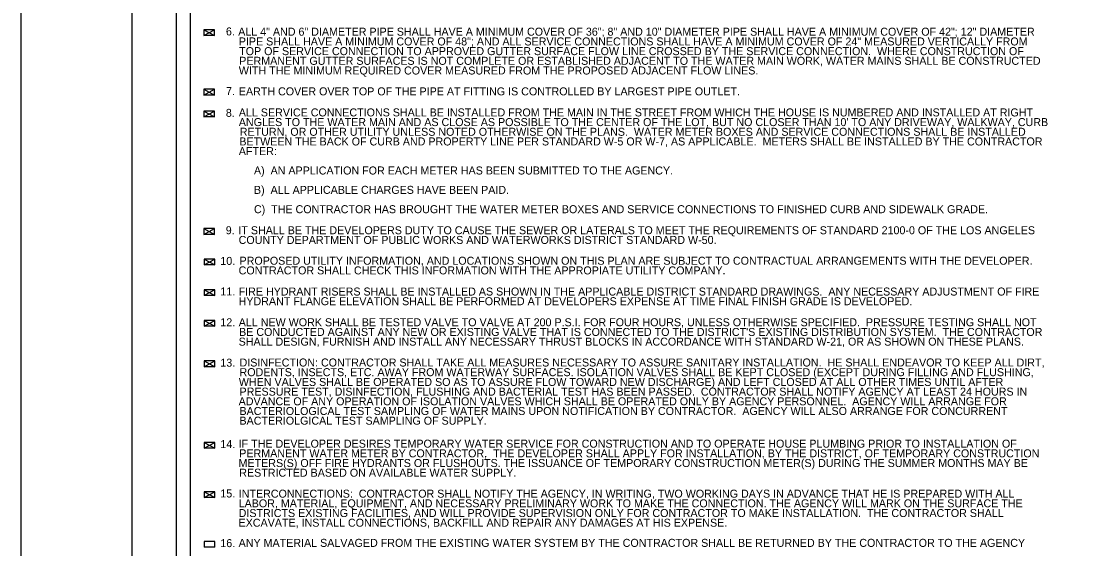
# Model space of a CAD drawing. Extents: x 837 to 1117, y 1316 to 1424.
# Drawn here: x 841.77 to 853.59, y 1410.3 to 1416.23 of the extents above; entities that cross this region are included whole.
import ezdxf

# ---------------------------------------------------------------- set-up
doc = ezdxf.new("R2010")
doc.units = 0
for name, color, linetype in [('0 (Construction)', 7, 'Continuous'), ('BASEMAP', 7, 'Continuous'), ('LLINES', 7, 'Continuous'), ('TEXT', 7, 'Continuous')]:
    doc.layers.add(name, color=color, linetype=linetype)

msp = doc.modelspace()

# ---------------------------------------------------------------- linework, layer by layer
at = {"layer": '0 (Construction)'}
msp.add_lwpolyline([(841.77, 1422.24), (877.77, 1422.24), (877.77, 1398.24), (841.77, 1398.24)], close=True, dxfattribs=at)
at = {"layer": 'BASEMAP'}
for p, q in [((843.02, 1399.24), (843.02, 1421.24)), ((843.52, 1399.74), (843.52, 1420.74)), ((843.678, 1399.867), (843.678, 1420.065))]:
    msp.add_line(p, q, dxfattribs=at)
at = {"layer": 'LLINES'}
for p, q in [((843.828, 1416.133), (843.948, 1416.069)), ((843.828, 1416.133), (843.828, 1416.069)), ((843.828, 1416.069), (843.948, 1416.133)), ((843.948, 1416.133), (843.828, 1416.133)), ((843.948, 1416.069), (843.828, 1416.069)), ((843.948, 1416.069), (843.948, 1416.133)), ((843.828, 1415.397), (843.948, 1415.462)), ((843.828, 1415.462), (843.828, 1415.397)), ((843.828, 1415.462), (843.948, 1415.397)), ((843.948, 1415.462), (843.828, 1415.462)), ((843.948, 1415.397), (843.828, 1415.397)), ((843.948, 1415.397), (843.948, 1415.462)), ((843.828, 1415.152), (843.948, 1415.216)), ((843.828, 1415.216), (843.948, 1415.152)), ((843.948, 1415.216), (843.828, 1415.216)), ((843.828, 1415.216), (843.828, 1415.152)), ((843.948, 1415.152), (843.828, 1415.152)), ((843.948, 1415.152), (843.948, 1415.216)), ((843.827, 1413.829), (843.946, 1413.894)), ((843.827, 1413.894), (843.827, 1413.829)), ((843.827, 1413.894), (843.946, 1413.829)), ((843.946, 1413.894), (843.827, 1413.894)), ((843.946, 1413.829), (843.827, 1413.829)), ((843.946, 1413.829), (843.946, 1413.894)), ((843.949, 1413.55), (843.83, 1413.55)), ((843.83, 1413.55), (843.949, 1413.485)), ((843.83, 1413.55), (843.83, 1413.485)), ((843.83, 1413.485), (843.949, 1413.55)), ((843.949, 1413.485), (843.83, 1413.485)), ((843.949, 1413.485), (843.949, 1413.55)), ((843.83, 1413.206), (843.83, 1413.141)), ((843.949, 1413.206), (843.83, 1413.206)), ((843.949, 1413.141), (843.83, 1413.141)), ((843.949, 1413.141), (843.949, 1413.206)), ((843.949, 1412.858), (843.83, 1412.858)), ((843.83, 1412.858), (843.949, 1412.794)), ((843.83, 1412.858), (843.83, 1412.794)), ((843.83, 1412.794), (843.949, 1412.858)), ((843.949, 1412.794), (843.83, 1412.794)), ((843.949, 1412.794), (843.949, 1412.858)), ((843.83, 1412.339), (843.949, 1412.404)), ((843.83, 1412.404), (843.83, 1412.339)), ((843.83, 1412.404), (843.949, 1412.339)), ((843.949, 1412.404), (843.83, 1412.404)), ((843.949, 1412.339), (843.949, 1412.404)), ((843.949, 1412.339), (843.83, 1412.339)), ((843.949, 1411.487), (843.83, 1411.487)), ((843.83, 1411.487), (843.949, 1411.422)), ((843.83, 1411.487), (843.83, 1411.422)), ((843.83, 1411.422), (843.949, 1411.487)), ((843.949, 1411.422), (843.949, 1411.487)), ((843.949, 1411.422), (843.83, 1411.422)), ((843.83, 1410.866), (843.949, 1410.93)), ((843.83, 1410.93), (843.83, 1410.866)), ((843.83, 1410.93), (843.949, 1410.866)), ((843.949, 1410.93), (843.83, 1410.93)), ((843.949, 1410.866), (843.83, 1410.866)), ((843.949, 1410.866), (843.949, 1410.93)), ((843.949, 1410.372), (843.83, 1410.372)), ((843.83, 1410.372), (843.83, 1410.307)), ((843.949, 1410.307), (843.83, 1410.307)), ((843.949, 1410.307), (843.949, 1410.372))]:
    msp.add_line(p, q, dxfattribs=at)
at = {"layer": 'TEXT'}
for p, q in [((843.949, 1413.206), (843.83, 1413.141)), ((843.83, 1413.206), (843.949, 1413.141))]:
    msp.add_line(p, q, dxfattribs=at)

# ---------------------------------------------------------------- texts
at = {"layer": 'LLINES'}
for s, p in [('6.', (844.075, 1416.069)), ('ALL 4" AND 6" DIAMETER PIPE SHALL HAVE A MINIMUM COVER OF 36"; 8" AND 10" DIAMETER PIPE SHALL HAVE A MINIMUM COVER OF 42"; 12" DIAMETER', (844.213, 1416.066)), ('TOP OF SERVICE CONNECTION TO APPROVED GUTTER SURFACE FLOW LINE CROSSED BY THE SERVICE CONNECTION.  WHERE CONSTRUCTION OF', (844.224, 1415.847)), ('PIPE SHALL HAVE A MINIMUM COVER OF 48"; AND ALL SERVICE CONNECTIONS SHALL HAVE A MINIMUM COVER OF 24" MEASURED VERTICALLY FROM', (844.22, 1415.956)), ('PERMANENT GUTTER SURFACES IS NOT COMPLETE OR ESTABLISHED ADJACENT TO THE WATER MAIN WORK, WATER MAINS SHALL BE CONSTRUCTED', (844.225, 1415.738)), ('WITH THE MINIMUM REQUIRED COVER MEASURED FROM THE PROPOSED ADJACENT FLOW LINES.', (844.22, 1415.629)), ('7.', (844.076, 1415.397)), ('EARTH COVER OVER TOP OF THE PIPE AT FITTING IS CONTROLLED BY LARGEST PIPE OUTLET.', (844.22, 1415.394)), ('8.', (844.074, 1415.152)), ('ALL SERVICE CONNECTIONS SHALL BE INSTALLED FROM THE MAIN IN THE STREET FROM WHICH THE HOUSE IS NUMBERED AND INSTALLED AT RIGHT', (844.22, 1415.157)), ("ANGLES TO THE WATER MAIN AND AS CLOSE AS POSSIBLE TO THE CENTER OF THE LOT, BUT NO CLOSER THAN 10' TO ANY DRIVEWAY, WALKWAY, CURB", (844.22, 1415.048)), ('RETURN, OR OTHER UTILITY UNLESS NOTED OTHERWISE ON THE PLANS.  WATER METER BOXES AND SERVICE CONNECTIONS SHALL BE INSTALLED', (844.231, 1414.939)), ('BETWEEN THE BACK OF CURB AND PROPERTY LINE PER STANDARD W-5 OR W-7, AS APPLICABLE.  METERS SHALL BE INSTALLED BY THE CONTRACTOR', (844.226, 1414.83)), ('AFTER:', (844.22, 1414.721)), ('     A)  AN APPLICATION FOR EACH METER HAS BEEN SUBMITTED TO THE AGENCY.', (844.223, 1414.503)), ('     B)  ALL APPLICABLE CHARGES HAVE BEEN PAID.', (844.223, 1414.285)), ('     C)  THE CONTRACTOR HAS BROUGHT THE WATER METER BOXES AND SERVICE CONNECTIONS TO FINISHED CURB AND SIDEWALK GRADE.', (844.223, 1414.067)), ('9.', (844.073, 1413.83)), ('COUNTY DEPARTMENT OF PUBLIC WORKS AND WATERWORKS DISTRICT STANDARD W-50.', (844.218, 1413.721)), ('IT SHALL BE THE DEVELOPERS DUTY TO CAUSE THE SEWER OR LATERALS TO MEET THE REQUIREMENTS OF STANDARD 2100-0 OF THE LOS ANGELES', (844.215, 1413.83)), ('10.', (844.012, 1413.485)), ('PROPOSED UTILITY INFORMATION, AND LOCATIONS SHOWN ON THIS PLAN ARE SUBJECT TO CONTRACTUAL ARRANGEMENTS WITH THE DEVELOPER.', (844.228, 1413.487)), ('CONTRACTOR SHALL CHECK THIS INFORMATION WITH THE APPROPIATE UTILITY COMPANY.', (844.218, 1413.378)), ('11.', (844.012, 1413.141)), ('FIRE HYDRANT RISERS SHALL BE INSTALLED AS SHOWN IN THE APPLICABLE DISTRICT STANDARD DRAWINGS.  ANY NECESSARY ADJUSTMENT OF FIRE', (844.218, 1413.14)), ('HYDRANT FLANGE ELEVATION SHALL BE PERFORMED AT DEVELOPERS EXPENSE AT TIME FINAL FINISH GRADE IS DEVELOPED.', (844.218, 1413.031)), ('12.', (844.012, 1412.794)), ('ALL NEW WORK SHALL BE TESTED VALVE TO VALVE AT 200 P.S.I. FOR FOUR HOURS, UNLESS OTHERWISE SPECIFIED.  PRESSURE TESTING SHALL NOT', (844.219, 1412.794)), ("BE CONDUCTED AGAINST ANY NEW OR EXISTING VALVE THAT IS CONNECTED TO THE DISTRICT'S EXISTING DISTRIBUTION SYSTEM.  THE CONTRACTOR", (844.223, 1412.685)), ('SHALL DESIGN, FURNISH AND INSTALL ANY NECESSARY THRUST BLOCKS IN ACCORDANCE WITH STANDARD W-21, OR AS SHOWN ON THESE PLANS.', (844.218, 1412.576)), ('13.', (844.012, 1412.339)), ('DISINFECTION: CONTRACTOR SHALL TAKE ALL MEASURES NECESSARY TO ASSURE SANITARY INSTALLATION.  HE SHALL ENDEAVOR TO KEEP ALL DIRT,', (844.228, 1412.341)), ('RODENTS, INSECTS, ETC. AWAY FROM WATERWAY SURFACES. ISOLATION VALVES SHALL BE KEPT CLOSED (EXCEPT DURING FILLING AND FLUSHING,', (844.228, 1412.232)), ('WHEN VALVES SHALL BE OPERATED SO AS TO ASSURE FLOW TOWARD NEW DISCHARGE) AND LEFT CLOSED AT ALL OTHER TIMES UNTIL AFTER', (844.22, 1412.122)), ('PRESSURE TEST, DISINFECTION, FLUSHING AND BACTERIAL TEST HAS BEEN PASSED.  CONTRACTOR SHALL NOTIFY AGENCY AT LEAST 24 HOURS IN', (844.228, 1412.013)), ('ADVANCE OF ANY OPERATION OF ISOLATION VALVES WHICH SHALL BE OPERATED ONLY BY AGENCY PERSONNEL.  AGENCY WILL ARRANGE FOR', (844.218, 1411.904)), ('BACTERIOLOGICAL TEST SAMPLING OF WATER MAINS UPON NOTIFICATION BY CONTRACTOR.  AGENCY WILL ALSO ARRANGE FOR CONCURRENT', (844.227, 1411.795)), ('BACTERIOLGICAL TEST SAMPLING OF SUPPLY.', (844.227, 1411.686)), ('14.', (844.012, 1411.422)), ('IF THE DEVELOPER DESIRES TEMPORARY WATER SERVICE FOR CONSTRUCTION AND TO OPERATE HOUSE PLUMBING PRIOR TO INSTALLATION OF', (844.218, 1411.427)), ('PERMANENT WATER METER BY CONTRACTOR,  THE DEVELOPER SHALL APPLY FOR INSTALLATION, BY THE DISTRICT, OF TEMPORARY CONSTRUCTION', (844.225, 1411.318)), ('METERS(S) OFF FIRE HYDRANTS OR FLUSHOUTS. THE ISSUANCE OF TEMPORARY CONSTRUCTION METER(S) DURING THE SUMMER MONTHS MAY BE', (844.217, 1411.209)), ('RESTRICTED BASED ON AVAILABLE WATER SUPPLY.', (844.225, 1411.1)), ('15.', (844.012, 1410.866)), ('INTERCONNECTIONS:  CONTRACTOR SHALL NOTIFY THE AGENCY, IN WRITING, TWO WORKING DAYS IN ADVANCE THAT HE IS PREPARED WITH ALL', (844.219, 1410.864)), ('DISTRICTS EXISTING FACILITIES, AND WILL PROVIDE SUPERVISION ONLY FOR CONTRACTOR TO MAKE INSTALLATION.  THE CONTRACTOR SHALL', (844.218, 1410.646)), ('LABOR, MATERIAL, EQUIPMENT, AND NECESSARY PRELIMINARY WORK TO MAKE THE CONNECTION. THE AGENCY WILL MARK ON THE SURFACE THE', (844.218, 1410.755)), ('EXCAVATE, INSTALL CONNECTIONS, BACKFILL AND REPAIR ANY DAMAGES AT HIS EXPENSE.', (844.217, 1410.537)), ('16.', (844.012, 1410.307)), ('ANY MATERIAL SALVAGED FROM THE EXISTING WATER SYSTEM BY THE CONTRACTOR SHALL BE RETURNED BY THE CONTRACTOR TO THE AGENCY', (844.218, 1410.31))]:
    msp.add_text(s, height=0.09, dxfattribs=at).set_placement(p)

doc.saveas('drawing.dxf')
